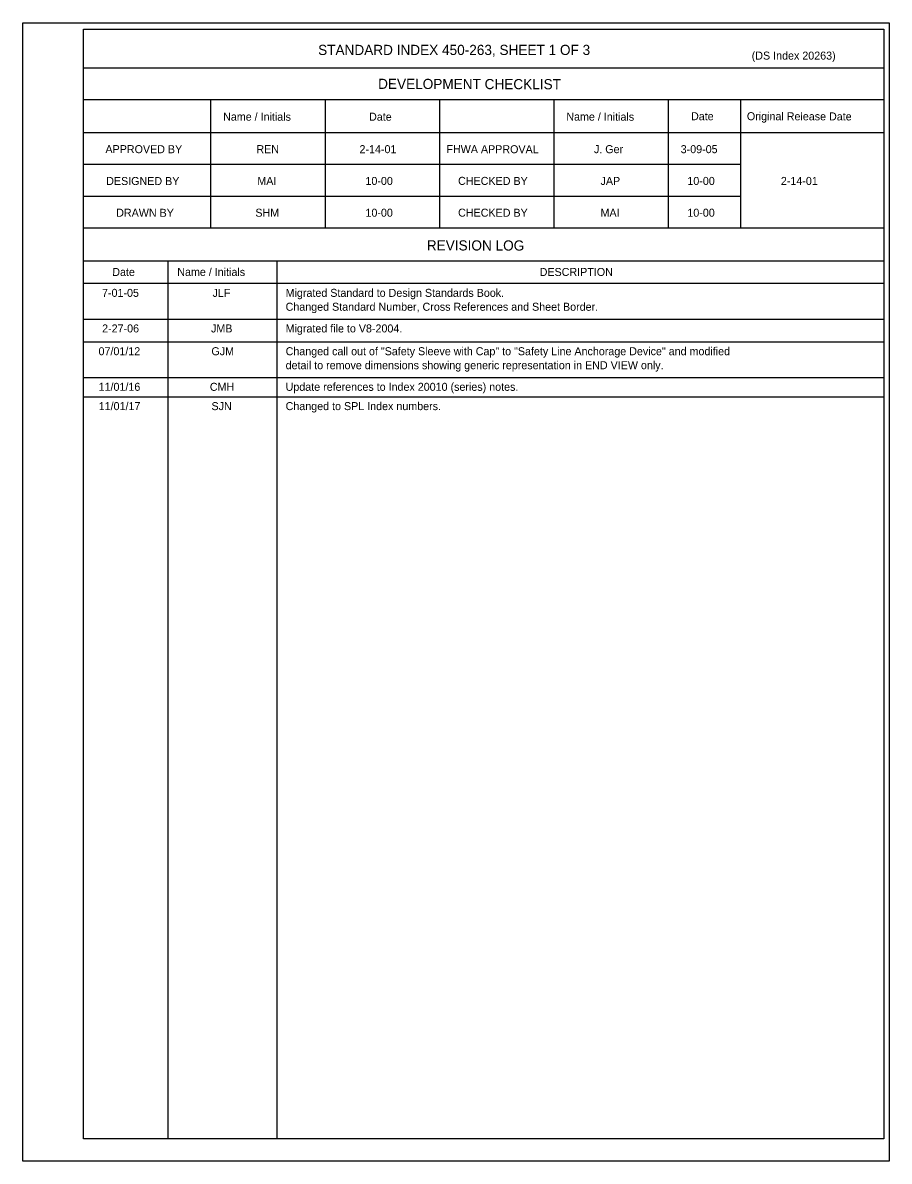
# Model space of a CAD drawing. Extents: x 120735 to 120771, y 120670.1 to 120685.4.
# Drawn here: x 120760.14 to 120771.05, y 120670.05 to 120684.39 of the extents above; entities that cross this region are included whole.
import ezdxf

# ---------------------------------------------------------------- set-up
doc = ezdxf.new("R2010")
doc.units = 0
for name, color, linetype in [('Border', 7, 'Continuous'), ('Dimension', 7, 'Continuous'), ('PlotBorder_dp', 7, 'Continuous'), ('TextStructures', 7, 'Continuous')]:
    doc.layers.add(name, color=color, linetype=linetype)

msp = doc.modelspace()

# ---------------------------------------------------------------- linework, layer by layer
at = {"layer": 'Border'}
for p, q in [((120770.978, 120683.815), (120760.904, 120683.815)), ((120770.978, 120683.415), (120760.904, 120683.415)), ((120762.504, 120683.415), (120762.504, 120681.801)), ((120763.944, 120683.415), (120763.944, 120681.801)), ((120765.384, 120683.415), (120765.384, 120681.801)), ((120766.824, 120683.415), (120766.824, 120681.801)), ((120768.264, 120683.415), (120768.264, 120681.801)), ((120769.172, 120683.415), (120769.172, 120681.801)), ((120770.978, 120683.001), (120760.904, 120683.001)), ((120769.172, 120682.601), (120760.904, 120682.601)), ((120769.172, 120682.201), (120760.904, 120682.201)), ((120770.978, 120681.801), (120760.904, 120681.801)), ((120770.978, 120681.387), (120760.904, 120681.387)), ((120761.965, 120681.387), (120761.965, 120670.334)), ((120763.336, 120681.387), (120763.336, 120670.334)), ((120770.978, 120681.105), (120760.904, 120681.105))]:
    msp.add_line(p, q, dxfattribs=at)
msp.add_lwpolyline([(120760.905, 120684.305), (120770.978, 120684.305), (120770.978, 120670.334), (120760.905, 120670.334)], close=True, dxfattribs=at)
at = {"layer": 'Dimension'}
for p, q in [((120760.904, 120680.657), (120770.978, 120680.657)), ((120760.904, 120680.37), (120770.978, 120680.37)), ((120760.904, 120679.922), (120770.978, 120679.922)), ((120760.904, 120679.679), (120770.978, 120679.679))]:
    msp.add_line(p, q, dxfattribs=at)
at = {"layer": 'PlotBorder_dp'}
msp.add_line((120760.139, 120670.053), (120760.139, 120670.053), dxfattribs=at)
msp.add_lwpolyline([(120760.139, 120684.387), (120771.046, 120684.387), (120771.046, 120670.053), (120760.139, 120670.053)], close=True, dxfattribs=at)

# ---------------------------------------------------------------- texts
at = {"layer": 'TextStructures'}
for s, height, p in [('STANDARD INDEX 450-263, SHEET 1 OF 3', 0.128, (120763.857, 120683.981)), ('(DS Index 20263)', 0.1008, (120769.315, 120683.923)), ('REN', 0.1008, (120763.08, 120682.745)), ('2-14-01', 0.1008, (120764.378, 120682.745)), ('J. Ger', 0.1008, (120767.329, 120682.745)), ('3-09-05', 0.1008, (120768.421, 120682.745)), ('MAI', 0.1008, (120763.092, 120682.345)), ('10-00', 0.1008, (120764.453, 120682.345)), ('JAP', 0.1008, (120767.412, 120682.345)), ('10-00', 0.1008, (120768.505, 120682.345)), ('2-14-01', 0.1008, (120769.682, 120682.345)), ('SHM', 0.1008, (120763.067, 120681.945)), ('10-00', 0.1008, (120764.453, 120681.945)), ('MAI', 0.1008, (120767.412, 120681.945)), ('10-00', 0.1008, (120768.505, 120681.945)), ('DESCRIPTION', 0.1008, (120766.646, 120681.199)), ('7-01-05', 0.1008, (120761.137, 120680.936)), ('JLF', 0.1008, (120762.528, 120680.936)), ('Migrated Standard to Design Standards Book.', 0.1008, (120763.448, 120680.936)), ('Changed Standard Number, Cross References and Sheet Border.', 0.1008, (120763.448, 120680.761)), ('2-27-06', 0.1008, (120761.138, 120680.488)), ('JMB', 0.1008, (120762.509, 120680.488)), ('Migrated file to V8-2004.', 0.1008, (120763.448, 120680.488)), ('07/01/12', 0.1008, (120761.093, 120680.201)), ('GJM', 0.1008, (120762.514, 120680.201)), ('Changed call out of "Safety Sleeve with Cap" to "Safety Line Anchorage Device" and modified', 0.1008, (120763.448, 120680.201)), ('detail to remove dimensions showing generic representation in END VIEW only.', 0.1008, (120763.448, 120680.025)), ('11/01/16', 0.1008, (120761.094, 120679.753)), ('CMH', 0.1008, (120762.494, 120679.753)), ('Update references to Index 20010 (series) notes.', 0.1008, (120763.448, 120679.753)), ('11/01/17', 0.1008, (120761.095, 120679.51)), ('SJN', 0.1008, (120762.515, 120679.51)), ('Changed to SPL Index numbers.', 0.1008, (120763.448, 120679.51))]:
    msp.add_text(s, height=height, dxfattribs=at).set_placement(p)
for s, height, p in [('DEVELOPMENT CHECKLIST', 0.128, (120764.612, 120683.554)), ('Name / Initials', 0.1008, (120762.661, 120683.155)), ('Date', 0.1008, (120764.498, 120683.154)), ('Name / Initials', 0.1008, (120766.981, 120683.155)), ('Date', 0.1008, (120768.551, 120683.16)), ('Original Release Date', 0.1008, (120769.254, 120683.16)), ('APPROVED BY', 0.1008, (120761.18, 120682.746)), ('FHWA APPROVAL', 0.1008, (120765.472, 120682.746)), ('DESIGNED BY', 0.1008, (120761.189, 120682.345)), ('CHECKED BY', 0.1008, (120765.619, 120682.346)), ('DRAWN BY', 0.1008, (120761.315, 120681.945)), ('CHECKED BY', 0.1008, (120765.619, 120681.946)), ('REVISION LOG', 0.128, (120765.225, 120681.521)), ('Date', 0.1008, (120761.266, 120681.199)), ('Name / Initials', 0.1008, (120762.084, 120681.2))]:
    msp.add_text(s, height=height, rotation=359.8756, dxfattribs=at).set_placement(p)

doc.saveas('drawing.dxf')
